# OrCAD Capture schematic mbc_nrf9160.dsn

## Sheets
1 01_BOARD: size Custom; rev: 1.0; note: 1.0
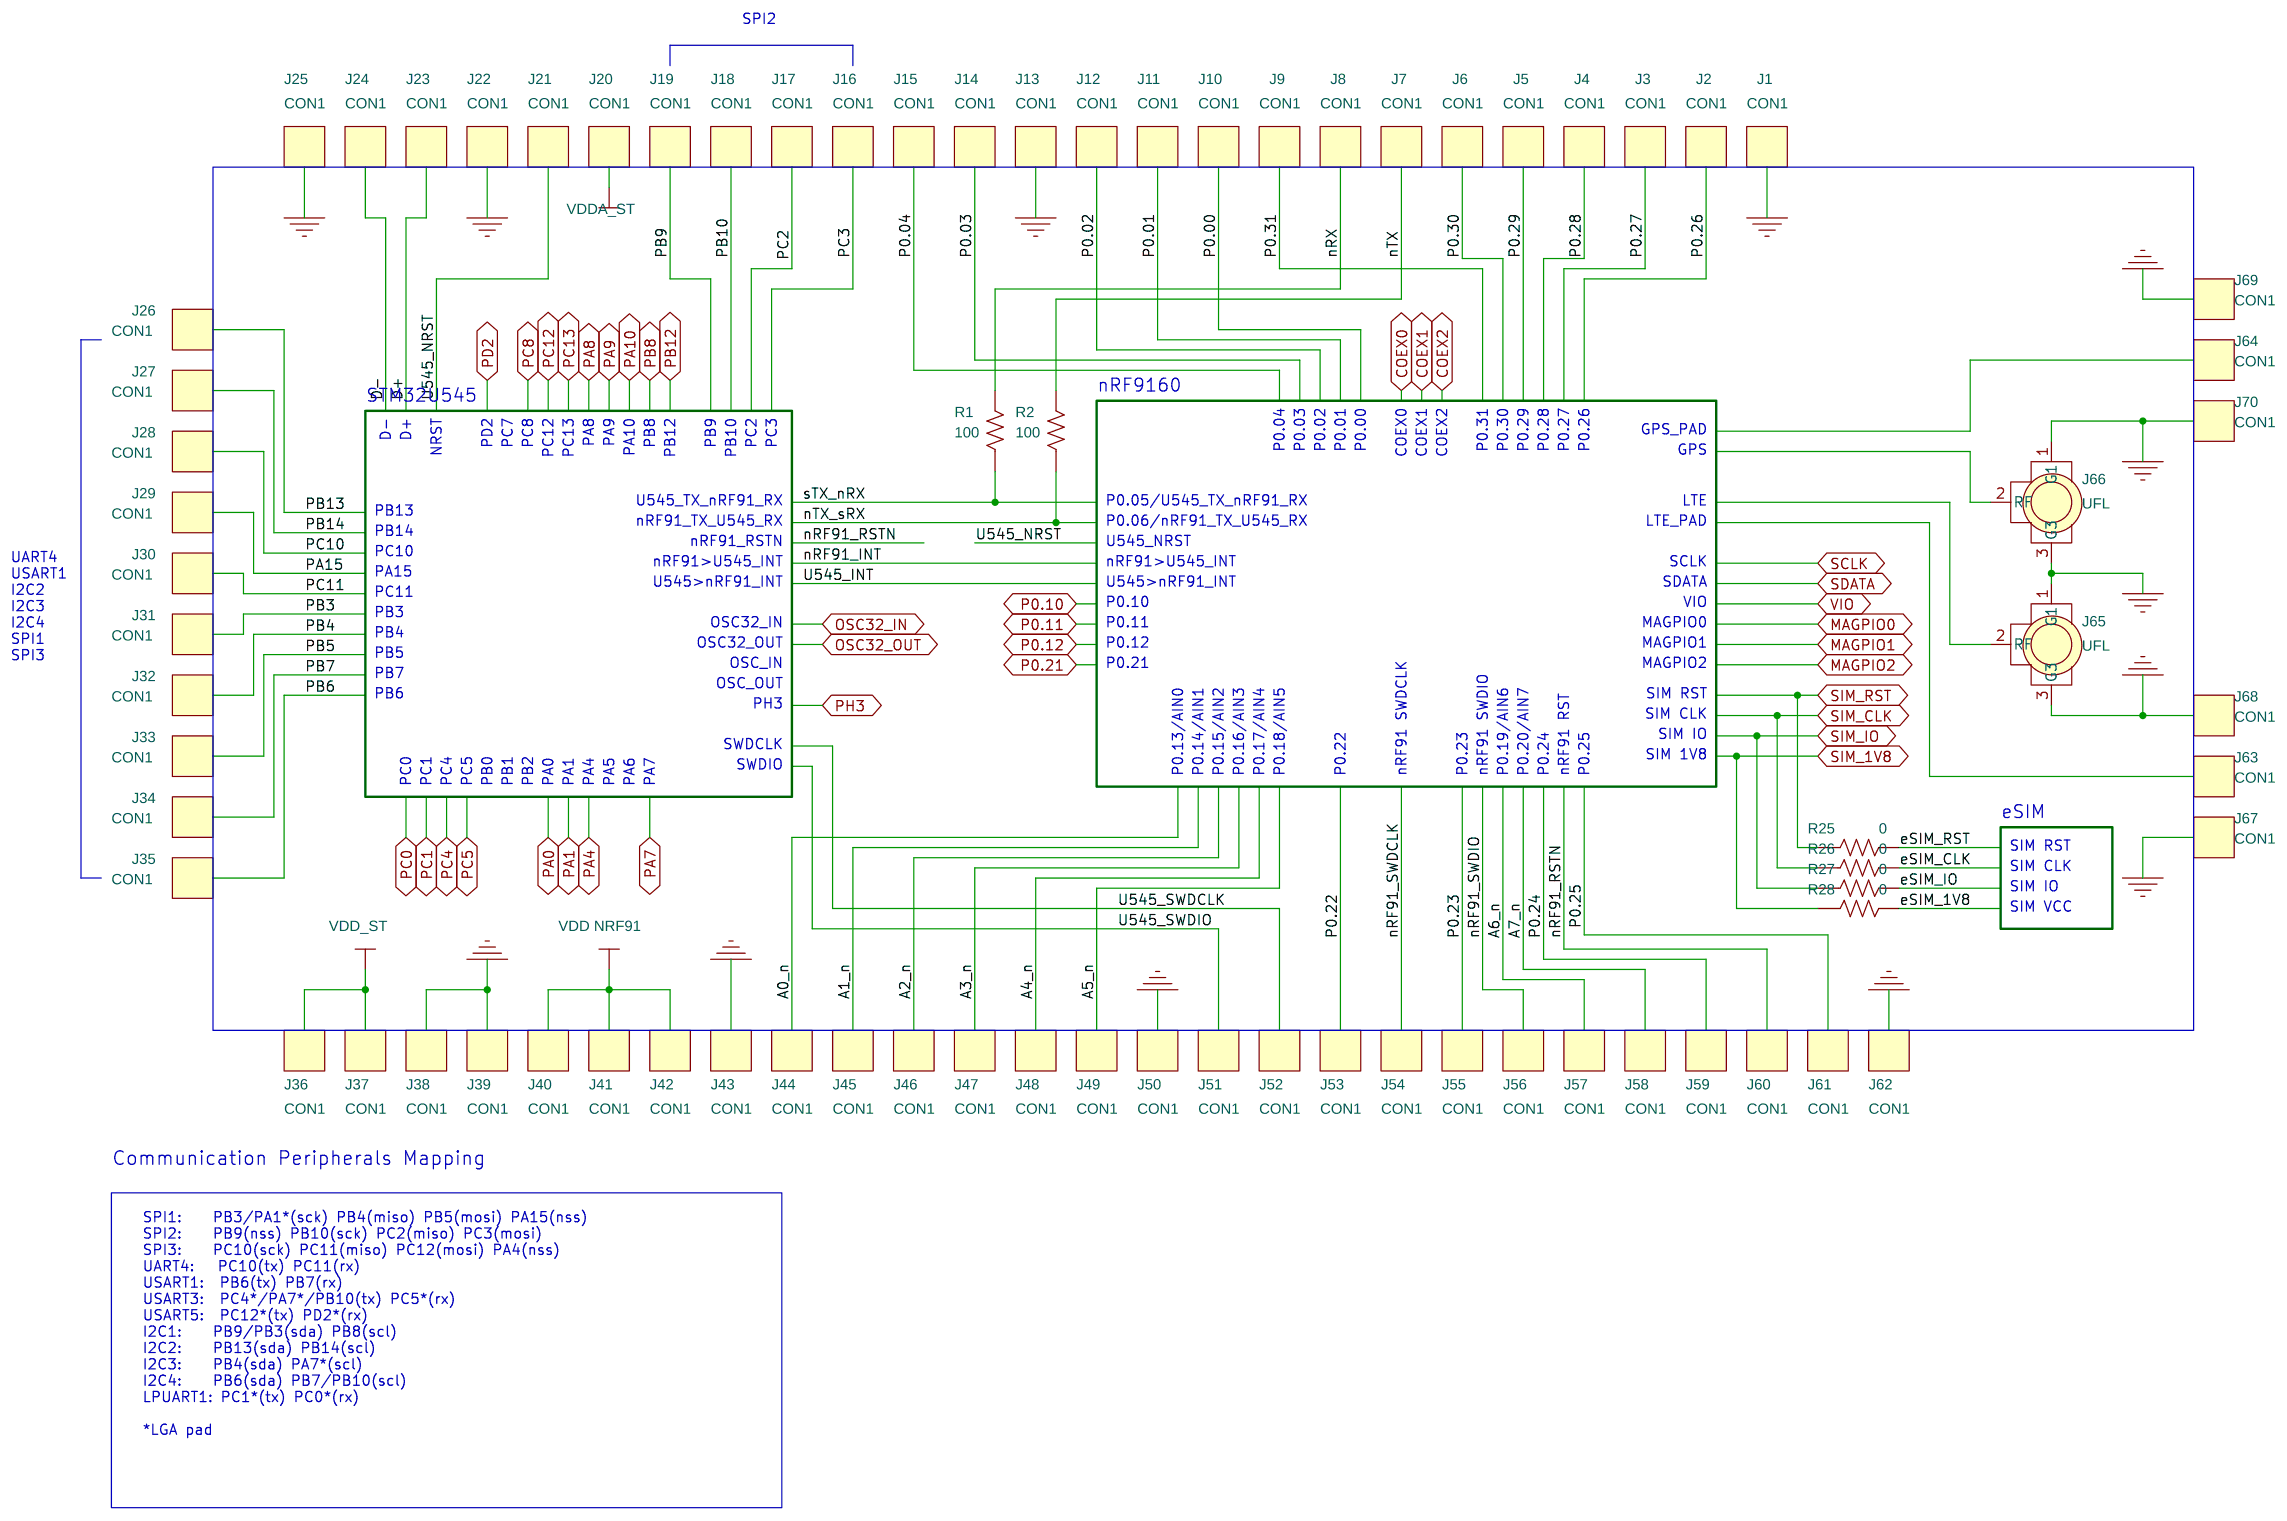
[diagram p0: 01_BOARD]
2 02_LGA: size Custom
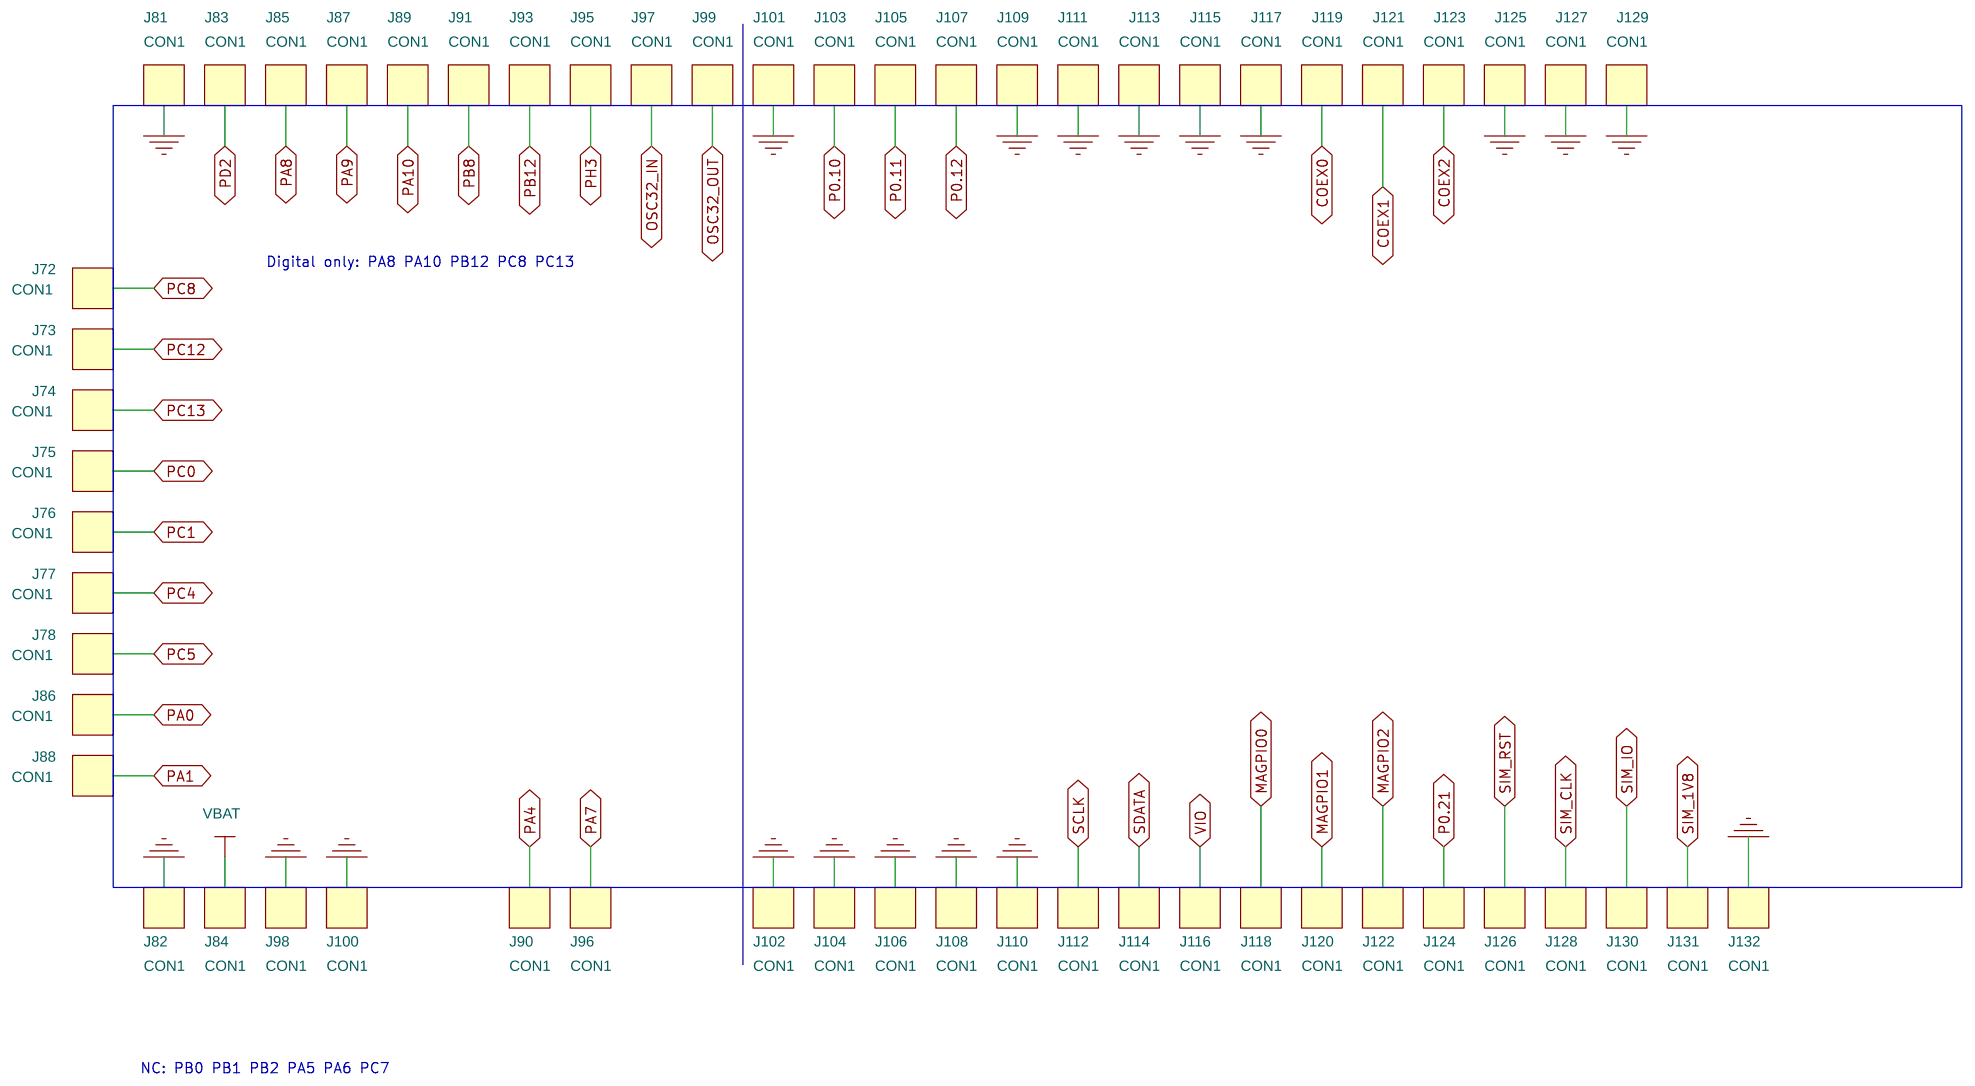
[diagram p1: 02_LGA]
3 eSIM: size A; block eSIM
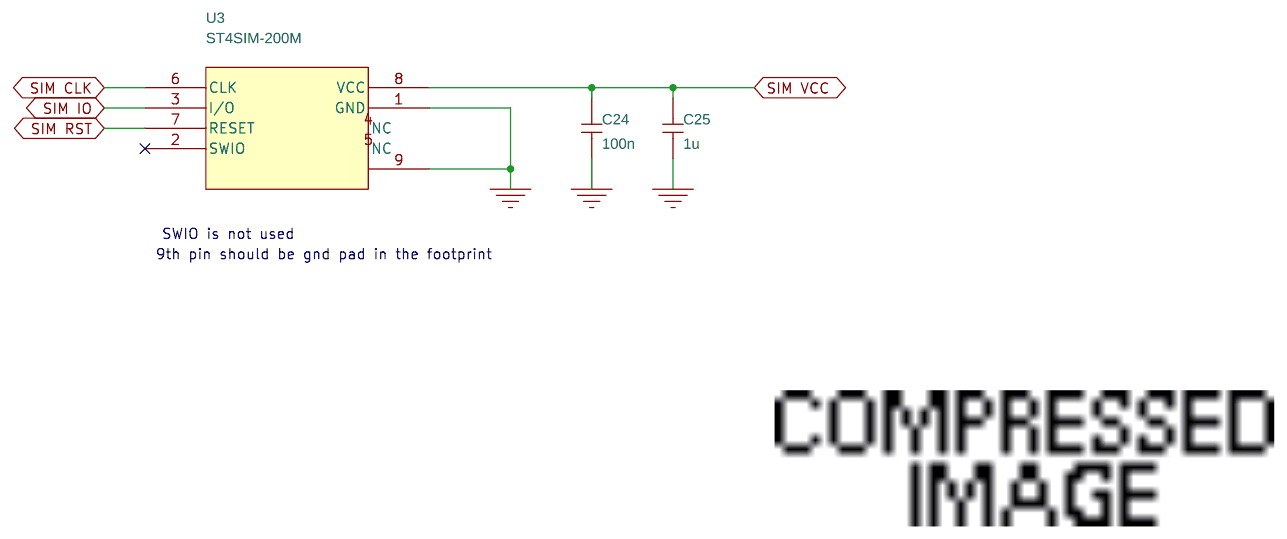
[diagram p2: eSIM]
4 NRF9160: size A; block nRF9160
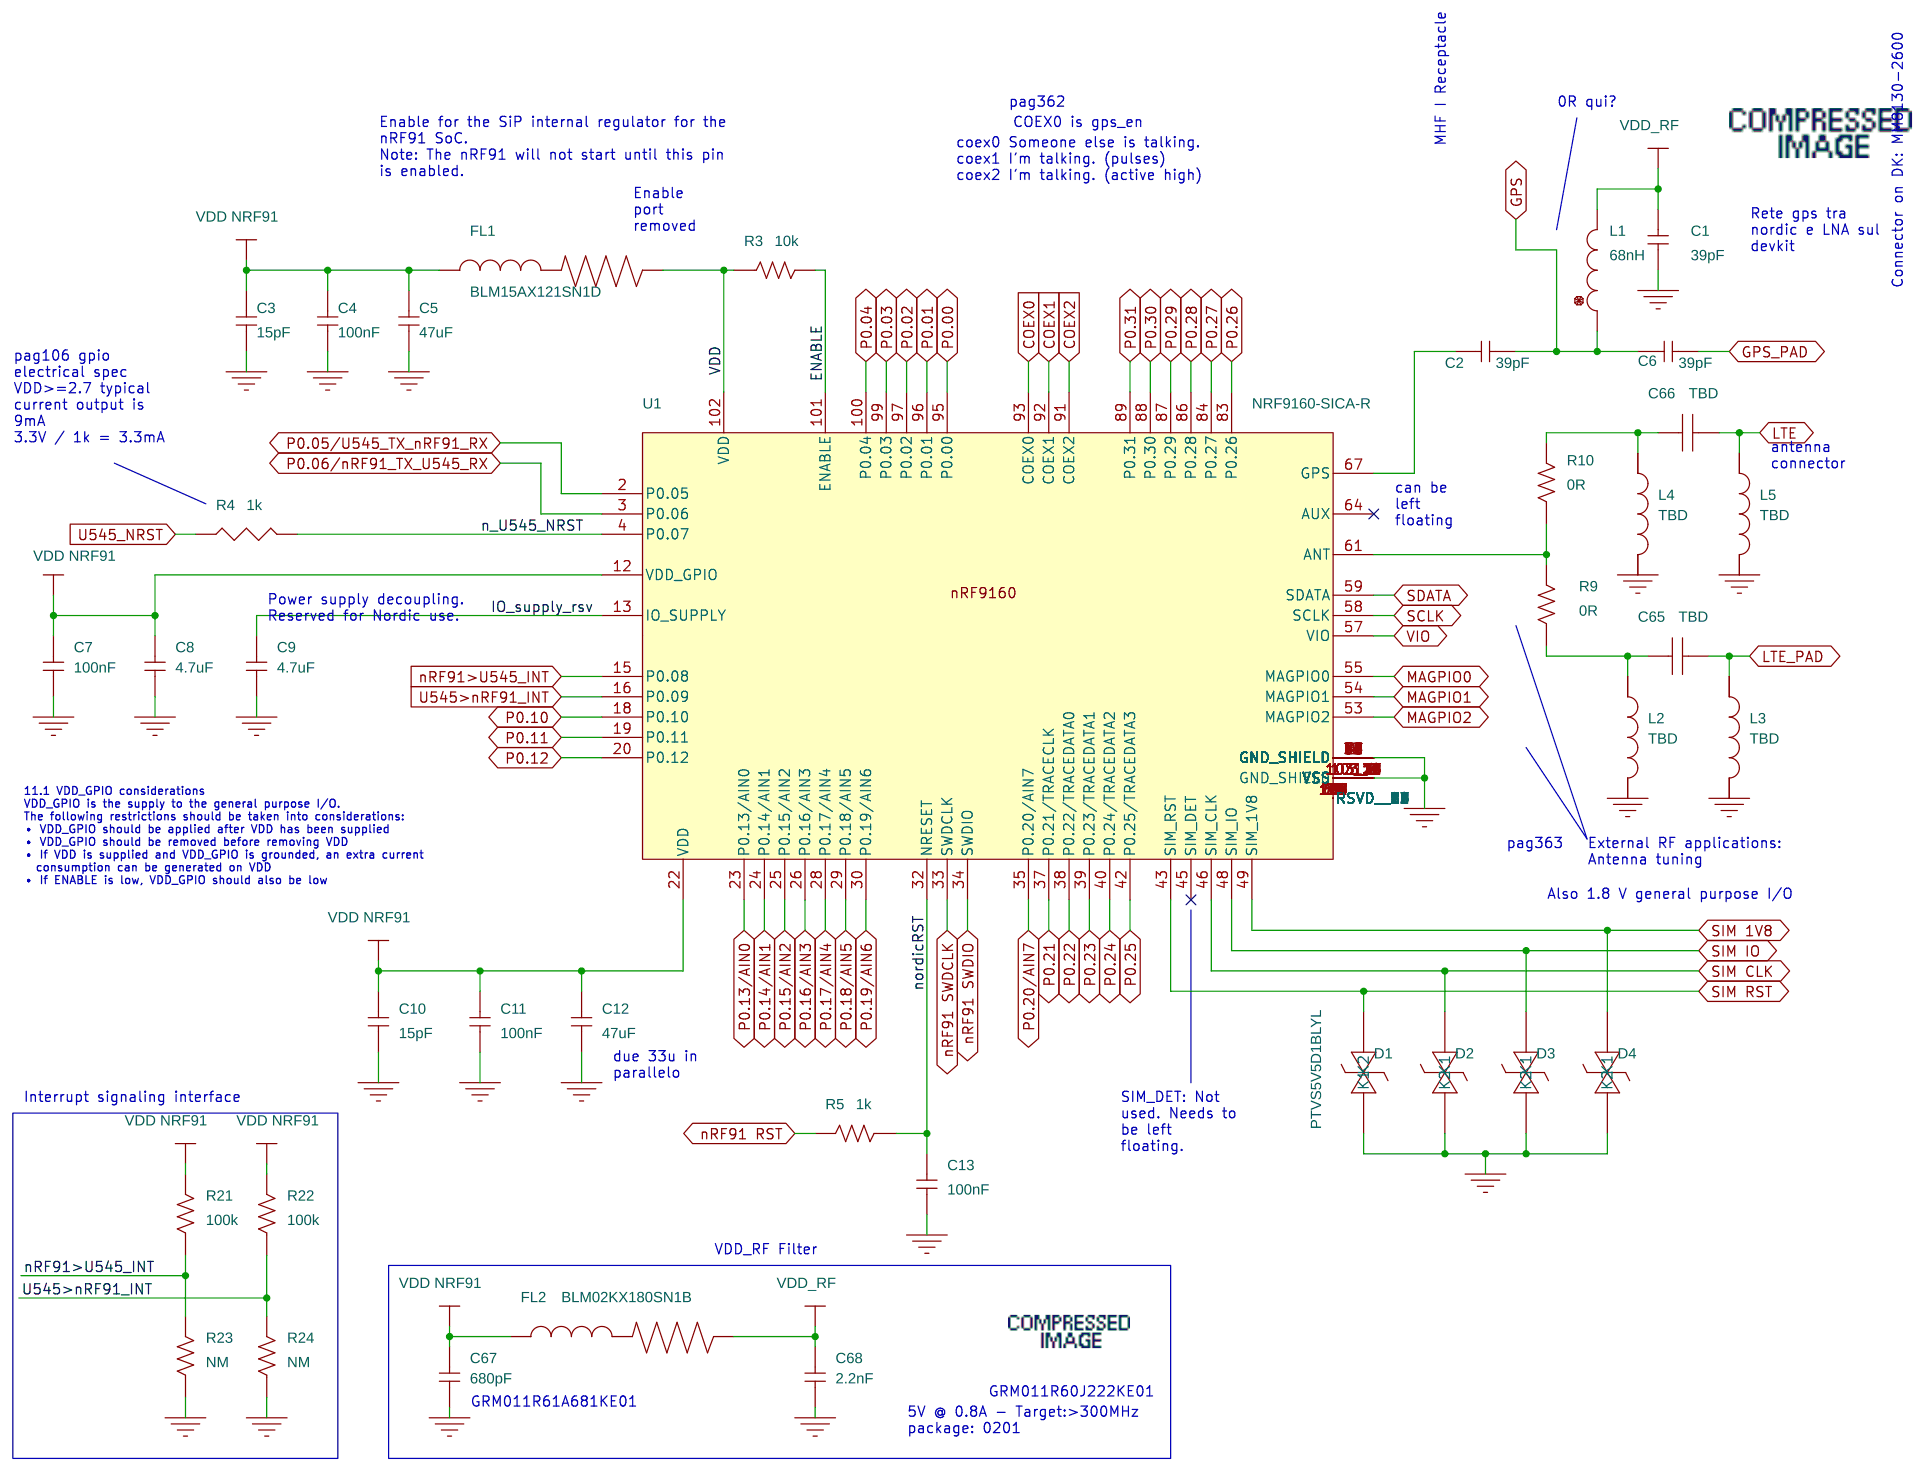
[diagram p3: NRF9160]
5 STM32U545: size A; block STM32U545
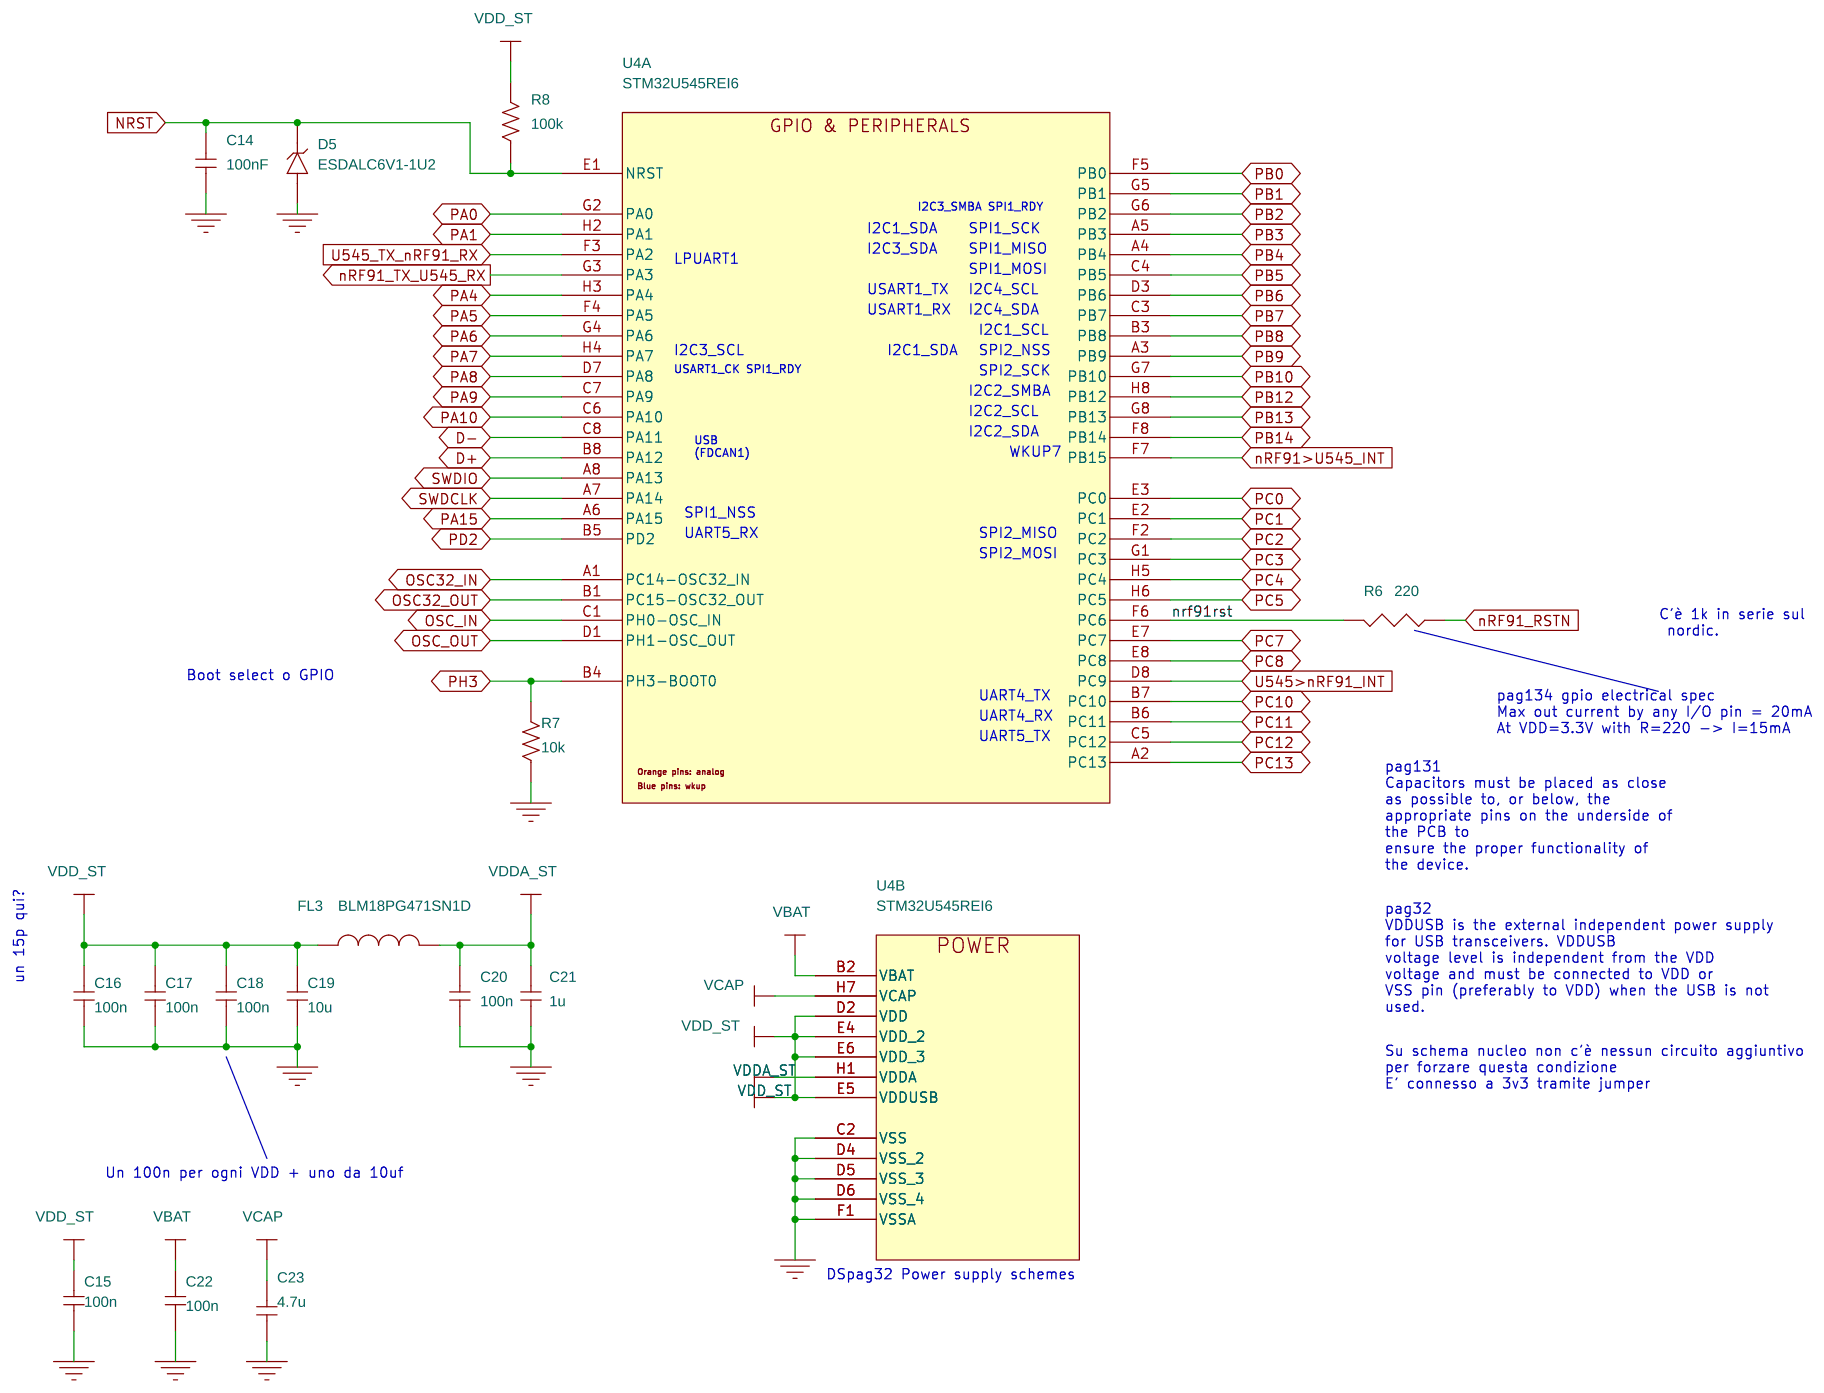
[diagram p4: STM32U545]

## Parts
sheet 01_BOARD
J1  CON1  [mbc_pad_conn]
J2  CON1  [mbc_pad_conn]
J3  CON1  [mbc_pad_conn]
J4  CON1  [mbc_pad_conn]
J5  CON1  [mbc_pad_conn]
J6  CON1  [mbc_pad_conn]
J7  CON1  [mbc_pad_conn]
J8  CON1  [mbc_pad_conn]
J9  CON1  [mbc_pad_conn]
J10  CON1  [mbc_pad_conn]
J11  CON1  [mbc_pad_conn]
J12  CON1  [mbc_pad_conn]
J13  CON1  [mbc_pad_conn]
J14  CON1  [mbc_pad_conn]
J15  CON1  [mbc_pad_conn]
J16  CON1  [mbc_pad_conn]
J17  CON1  [mbc_pad_conn]
J18  CON1  [mbc_pad_conn]
J19  CON1  [mbc_pad_conn]
J20  CON1  [mbc_pad_conn]
J21  CON1  [mbc_pad_conn]
J22  CON1  [mbc_pad_conn]
J23  CON1  [mbc_pad_conn]
J24  CON1  [mbc_pad_conn]
J25  CON1  [mbc_pad_conn]
J26  CON1  [mbc_pad_conn]
J27  CON1  [mbc_pad_conn]
J28  CON1  [mbc_pad_conn]
J29  CON1  [mbc_pad_conn]
J30  CON1  [mbc_pad_conn]
J31  CON1  [mbc_pad_conn]
J32  CON1  [mbc_pad_conn]
J33  CON1  [mbc_pad_conn]
J34  CON1  [mbc_pad_conn]
J35  CON1  [mbc_pad_conn]
J36  CON1  [mbc_pad_conn]
J37  CON1  [mbc_pad_conn]
J38  CON1  [mbc_pad_conn]
J39  CON1  [mbc_pad_conn]
J40  CON1  [mbc_pad_conn]
J41  CON1  [mbc_pad_conn]
J42  CON1  [mbc_pad_conn]
J43  CON1  [mbc_pad_conn]
J44  CON1  [mbc_pad_conn]
J45  CON1  [mbc_pad_conn]
J46  CON1  [mbc_pad_conn]
J47  CON1  [mbc_pad_conn]
J48  CON1  [mbc_pad_conn]
J49  CON1  [mbc_pad_conn]
J50  CON1  [mbc_pad_conn]
J51  CON1  [mbc_pad_conn]
J52  CON1  [mbc_pad_conn]
J53  CON1  [mbc_pad_conn]
J54  CON1  [mbc_pad_conn]
J55  CON1  [mbc_pad_conn]
J56  CON1  [mbc_pad_conn]
J57  CON1  [mbc_pad_conn]
J58  CON1  [mbc_pad_conn]
J59  CON1  [mbc_pad_conn]
J60  CON1  [mbc_pad_conn]
J61  CON1  [mbc_pad_conn]
J62  CON1  [mbc_pad_conn]
J63  CON1  [mbc_pad_conn]
J64  CON1  [mbc_pad_conn]
J65  UFL  [U_FL-R-SMT-1]
J66  UFL  [U_FL-R-SMT-1]
J67  CON1  [mbc_pad_conn]
J68  CON1  [mbc_pad_conn]
J69  CON1  [mbc_pad_conn]
J70  CON1  [mbc_pad_conn]
R1  100  [smr0201]
R2  100  [smr0201]
R25  0  [smr0201]
R26  0  [smr0201]
R27  0  [smr0201]
R28  0  [smr0201]
sheet 02_LGA
J72  CON1  [mbc_lga_small_pad]
J73  CON1  [mbc_lga_small_pad]
J74  CON1  [mbc_lga_small_pad]
J75  CON1  [mbc_lga_small_pad]
J76  CON1  [mbc_lga_small_pad]
J77  CON1  [mbc_lga_small_pad]
J78  CON1  [mbc_lga_small_pad]
J81  CON1  [mbc_lga_small_pad]
J82  CON1  [mbc_lga_small_pad]
J83  CON1  [mbc_lga_small_pad]
J84  CON1  [mbc_lga_small_pad]
J85  CON1  [mbc_lga_small_pad]
J86  CON1  [mbc_lga_small_pad]
J87  CON1  [mbc_lga_small_pad]
J88  CON1  [mbc_lga_small_pad]
J89  CON1  [mbc_lga_small_pad]
J90  CON1  [mbc_lga_small_pad]
J91  CON1  [mbc_lga_small_pad]
J93  CON1  [mbc_lga_small_pad]
J95  CON1  [mbc_lga_small_pad]
J96  CON1  [mbc_lga_small_pad]
J97  CON1  [mbc_lga_small_pad]
J98  CON1  [mbc_lga_small_pad]
J99  CON1  [mbc_lga_small_pad]
J100  CON1  [mbc_lga_small_pad]
J101  CON1  [mbc_lga_small_pad]
J102  CON1  [mbc_lga_small_pad]
J103  CON1  [mbc_lga_small_pad]
J104  CON1  [mbc_lga_small_pad]
J105  CON1  [mbc_lga_small_pad]
J106  CON1  [mbc_lga_small_pad]
J107  CON1  [mbc_lga_small_pad]
J108  CON1  [mbc_lga_small_pad]
J109  CON1  [mbc_lga_small_pad]
J110  CON1  [mbc_lga_small_pad]
J111  CON1  [mbc_lga_small_pad]
J112  CON1  [mbc_lga_small_pad]
J113  CON1  [mbc_lga_small_pad]
J114  CON1  [mbc_lga_small_pad]
J115  CON1  [mbc_lga_small_pad]
J116  CON1  [mbc_lga_small_pad]
J117  CON1  [mbc_lga_small_pad]
J118  CON1  [mbc_lga_small_pad]
J119  CON1  [mbc_lga_small_pad]
J120  CON1  [mbc_lga_small_pad]
J121  CON1  [mbc_lga_small_pad]
J122  CON1  [mbc_lga_small_pad]
J123  CON1  [mbc_lga_small_pad]
J124  CON1  [mbc_lga_small_pad]
J125  CON1  [mbc_lga_small_pad]
J126  CON1  [mbc_lga_small_pad]
J127  CON1  [mbc_lga_small_pad]
J128  CON1  [mbc_lga_small_pad]
J129  CON1  [mbc_lga_small_pad]
J130  CON1  [mbc_lga_small_pad]
J131  CON1  [mbc_lga_small_pad]
J132  CON1  [mbc_lga_small_pad]
sheet eSIM
C24  100n  [smc0402]
C25  1u  [smc0402]
U3  ST4SIM-200M  [SON_IM-200M_STM]
sheet NRF9160
C1  39pF  [smc0201]
C2  39pF  [smc0201]
C3  15pF  [smc0201]
C4  100nF  [smc0402]
C5  47uF  [smc0603]
C6  39pF  [smc0201]
C7  100nF  [smc0402]
C8  4.7uF  [smc0402]
C9  4.7uF  [smc0402]
C10  15pF  [smc0201]
C11  100nF  [smc0402]
C12  47uF  [smc0603]
C13  100nF  [smc0201]
C65  TBD  [smc0201]
C66  TBD  [smc0201]
C67  680pF  [smc0201]
C68  2.2nF  [smc0201]
D1  PTVS5V5D1BLYL  [PESD5V0S1BL315]
D2  PTVS5V5D1BLYL  [PESD5V0S1BL315]
D3  PTVS5V5D1BLYL  [PESD5V0S1BL315]
D4  PTVS5V5D1BLYL  [PESD5V0S1BL315]
FL1  BLM15AX121SN1D  [BEADC1005X55N]
FL2  BLM02KX180SN1B  [BEADC0402X32N]
L1  68nH  [sml0201]
L2  TBD  [sml0201]
L3  TBD  [sml0201]
L4  TBD  [sml0201]
L5  TBD  [sml0201]
R3  10k  [smr0201]
R4  1k  [smr0201]
R5  1k  [smr0201]
R9  0R  [smr0201]
R10  0R  [smr0201]
R21  100k  [smr0201]
R22  100k  [smr0201]
R23  NM  [smr0201]
R24  NM  [smr0201]
U1  NRF9160-SICA-R  [XCVR_NRF9160-SICA-R]
sheet STM32U545
C14  100nF  [smc0201]
C15  100n  [smc0402]
C16  100n  [smc0402]
C17  100n  [smc0402]
C18  100n  [smc0402]
C19  10u  [smc0603]
C20  100n  [smc0402]
C21  1u  [smc0402]
C22  100n  [smc0402]
C23  4.7u  [smc0402]
D5  ESDALC6V1-1U2  [DIODE_ESDALC6V1-1U2]
FL3  BLM18PG471SN1D  [sml0603]
R6  220  [smr0201]
R7  10k  [smr0201]
R8  100k  [smr0201]
U4  STM32U545REI6  [UFBGA64_5x5mm_STM]  (sections A,B)

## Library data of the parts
J1-J64 J67-J70 J72-J78 J81-J91 J93 J95-J132 = CON1_2
J65 J66 = UFL
R1-R3 R5 R7-R10 R21-R28 = R
C1-C25 C67 C68 = C
U3 = ST4SIM-200M_8
C65 C66 = CAP_NP_1
D1-D4 = PTVS5V5D1BLYL_0: Manufacturer Name: Nexperia; Source Id: SamacSys
FL1 = BLM15AX121SN1D: Manufacturer Name: Murata Electronics; Source Id: SnapEDA
FL2 = BLM02KX180SN1B: Manufacturer Name: Murata; Source Id: SnapEDA
L1 = L
FL3 L2-L5 = INDUCTOR
R4 R6 = R_0
U1 = myNRF9160-SICA-R_6
D5 = ESDALC6V1-1U2: Manufacturer Name: STMicroelectronics; Source Id: SnapEDA
U4 = STM32U545REI6_13

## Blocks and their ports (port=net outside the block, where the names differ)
STM32U545 = schematic STM32U545, on sheet 01_BOARD: D-, D+, U545_TX_nRF91_RX=sTX_nRX, nRF91_TX_U545_RX=nTX_sRX, nRF91_RSTN, NRST=U545_NRST, nRF91>U545_INT=nRF91_INT, U545>nRF91_INT=U545_INT, SWDCLK=U545_SWDCLK, SWDIO=U545_SWDIO, PA15, PB14, PB5, PA7, PB4, PB7, PB6, PB13, PC11, PC10, PB3, PB2=open, PH3, PC2, PB9, PC3, PB10, PB1=open, PB0=open, OSC_OUT=open, OSC32_OUT, OSC32_IN, OSC_IN=open, PA8, PA9, PA10, PC12, PC8, PD2, PB8, PC7=open, PB12, PC13, PC0, PC1, PC4, PC5, PA4, PA5=open, PA6=open, PA0, PA1
eSIM = schematic ST4SIM-200M, on sheet 01_BOARD: SIM CLK=eSIM_CLK, SIM VCC=eSIM_1V8, SIM IO=eSIM_IO, SIM RST=eSIM_RST
nRF9160 = schematic NRF9160, on sheet 01_BOARD: P0.13/AIN0=A0_n, P0.14/AIN1=A1_n, P0.15/AIN2=A2_n, P0.16/AIN3=A3_n, P0.17/AIN4=A4_n, P0.18/AIN5=A5_n, P0.19/AIN6=A6_n, P0.20/AIN7=A7_n, P0.21, P0.22, P0.23, P0.24, P0.25, P0.10, P0.11, P0.12, P0.04, P0.03, P0.02, P0.01, P0.00, P0.31, P0.30, P0.29, P0.28, P0.27, P0.26, nRF91 RST=nRF91_RSTN, nRF91 SWDCLK=nRF91_SWDCLK, nRF91 SWDIO=nRF91_SWDIO, SIM RST=SIM_RST, SIM CLK=SIM_CLK, SIM IO=SIM_IO, SIM 1V8=SIM_1V8, SDATA, SCLK, VIO, P0.05/U545_TX_nRF91_RX=sTX_nRX, P0.06/nRF91_TX_U545_RX=nTX_sRX, nRF91>U545_INT=nRF91_INT, U545>nRF91_INT=U545_INT, U545_NRST, COEX0, COEX1, COEX2, MAGPIO2, MAGPIO0, MAGPIO1, LTE=N13625908, LTE_PAD=N13629219, GPS=N13629615, GPS_PAD=N13629622

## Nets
GND: C1.1 C3.1 C4.1 C5.1 C7.1 C8.1 C9.1 C10.1 C11.1 C12.1 C13.1 C14.1 C15.1 C16.1 C17.1 C18.1 C19.1 C20.1 C21.1 C22.1 C23.1 C24.1 C25.1 C67.1 C68.1 D1.1(K1) D2.2(K2) D3.2(K2) D4.2(K2) D5.2(A) J1.1 J13.1 J22.1 J25.1 J38.1 J39.1 J43.1 J50.1 J62.1 J65.1(G1) J65.3(G3) J66.1(G1) J66.3(G3) J67.1 J68.1 J69.1 J70.1 J81.1 J82.1 J98.1 J100.1 J101.1 J102.1 J104.1 J106.1 J108.1 J109.1 J110.1 J111.1 J113.1 J115.1 J117.1 J125.1 J127.1 J129.1 J132.1 L2.2 L3.2 L4.2 L5.2 R7.1 R23.1 R24.1 U1.1(GND_SHIELD) U1.103_1(VSS) U3.1(GND) U3.9 U4.C2(VSS) U4.D4(VSS_2) U4.D5(VSS_3) U4.D6(VSS_4) U4.F1(VSSA)
nRF9160/GND_SHIELD: U1.5(GND_SHIELD) U1.9(GND_SHIELD) U1.14(GND_SHIELD) U1.17(GND_SHIELD) U1.21(GND_SHIELD) U1.27(GND_SHIELD) U1.31(GND_SHIELD) U1.36(GND_SHIELD) U1.41(GND_SHIELD) U1.44(GND_SHIELD) U1.47(GND_SHIELD) U1.50(GND_SHIELD) U1.52(GND_SHIELD) U1.56(GND_SHIELD) U1.60(GND_SHIELD) U1.62(GND_SHIELD) U1.63(GND_SHIELD) U1.65(GND_SHIELD) U1.66(GND_SHIELD) U1.72(GND_SHIELD) U1.74(GND_SHIELD) U1.75(GND_SHIELD) U1.76(GND_SHIELD) U1.77(GND_SHIELD) U1.78(GND_SHIELD) U1.79(GND_SHIELD) U1.80(GND_SHIELD) U1.81(GND_SHIELD) U1.82(GND_SHIELD) U1.85(GND_SHIELD) U1.90(GND_SHIELD) U1.94(GND_SHIELD) U1.98(GND_SHIELD)
nRF9160/VDD: FL1.2 R3.1 U1.102(VDD)
nRF9160/VSS: U1.103_2(VSS) U1.103_3(VSS) U1.103_4(VSS) U1.103_5(VSS) U1.103_6(VSS) U1.103_7(VSS) U1.103_8(VSS) U1.103_9(VSS) U1.103_10(VSS) U1.103_11(VSS) U1.103_12(VSS) U1.103_13(VSS) U1.103_14(VSS) U1.103_15(VSS) U1.103_16(VSS) U1.103_17(VSS) U1.103_18(VSS) U1.103_19(VSS) U1.103_20(VSS) U1.103_21(VSS) U1.103_22(VSS) U1.103_23(VSS) U1.103_24(VSS) U1.103_25(VSS) U1.103_26(VSS) U1.103_27(VSS) U1.103_28(VSS) U1.103_29(VSS) U1.103_30(VSS) U1.103_31(VSS) U1.103_32(VSS) U1.103_33(VSS) U1.103_34(VSS) U1.103_35(VSS)
VBAT: C22.2 J84.1 U4.B2(VBAT)
VDD nRF91: C3.2 C4.2 C5.2 C7.2 C8.2 C10.2 C11.2 C12.2 C67.2 FL1.1 FL2.1 J40.1 J41.1 J42.1 R21.2 R22.2 U1.12(VDD_GPIO) U1.22(VDD)
VDD_RF: C1.2 C68.2 FL2.2 L1.2
VDD_ST: C15.2 C16.2 C17.2 C18.2 C19.2 FL3.1 J36.1 J37.1 R8.2 U4.D2(VDD) U4.E4(VDD_2) U4.E5(VDDUSB) U4.E6(VDD_3)
VDDA_ST: C20.2 C21.2 FL3.2 J20.1 U4.H1(VDDA)
A0_n: J44.1 U1.23(P0.13/AIN0)
A1_n: J45.1 U1.24(P0.14/AIN1)
A2_n: J46.1 U1.25(P0.15/AIN2)
A3_n: J47.1 U1.26(P0.16/AIN3)
A4_n: J48.1 U1.28(P0.17/AIN4)
A5_n: J49.1 U1.29(P0.18/AIN5)
A6_n: J57.1 U1.30(P0.19/AIN6)
A7_n: J58.1 U1.35(P0.20/AIN7)
COEX0: J119.1 U1.93(COEX0)
COEX1: J121.1 U1.92(COEX1)
COEX2: J123.1 U1.91(COEX2)
D+: J23.1 U4.B8(PA12)
D-: J24.1 U4.C8(PA11)
eSIM_1V8: C24.2 C25.2 R28.2 U3.8(VCC)
eSIM_CLK: R26.2 U3.6(CLK)
eSIM_IO: R27.2 U3.3(I/O)
eSIM_RST: R25.2 U3.7(RESET)
MAGPIO0: J118.1 U1.55(MAGPIO0)
MAGPIO1: J120.1 U1.54(MAGPIO1)
MAGPIO2: J122.1 U1.53(MAGPIO2)
NC: U3.4(NC) U3.5(NC)
nRF91_INT: R21.1 R23.2 U1.15(P0.08) U4.F7(PB15)
nRF91_RSTN: J60.1 R5.2 R6.1
nRF91_SWDCLK: J54.1 U1.33(SWDCLK)
nRF91_SWDIO: J56.1 U1.34(SWDIO)
nRF9160/ENABLE: R3.2 U1.101(ENABLE)
nRF9160/IO_supply_rsv: C9.2 U1.13(IO_SUPPLY)
nRF9160/n_U545_NRST: R4.2 U1.4(P0.07)
nRF9160/nordicRST: C13.2 R5.1 U1.32(NRESET)
nRX: J8.1 R1.2
nTX: J7.1 R2.2
nTX_sRX: R2.1 U1.3(P0.06) U4.G3(PA3)
OSC32_IN: J97.1 U4.A1(PC14-OSC32_IN)
OSC32_OUT: J99.1 U4.B1(PC15-OSC32_OUT)
P0.00: J10.1 U1.95(P0.00)
P0.01: J11.1 U1.96(P0.01)
P0.02: J12.1 U1.97(P0.02)
P0.03: J14.1 U1.99(P0.03)
P0.04: J15.1 U1.100(P0.04)
P0.10: J103.1 U1.18(P0.10)
P0.11: J105.1 U1.19(P0.11)
P0.12: J107.1 U1.20(P0.12)
P0.21: J124.1 U1.37(P0.21/TRACECLK)
P0.22: J53.1 U1.38(P0.22/TRACEDATA0)
P0.23: J55.1 U1.39(P0.23/TRACEDATA1)
P0.24: J59.1 U1.40(P0.24/TRACEDATA2)
P0.25: J61.1 U1.42(P0.25/TRACEDATA3)
P0.26: J2.1 U1.83(P0.26)
P0.27: J3.1 U1.84(P0.27)
P0.28: J4.1 U1.86(P0.28)
P0.29: J5.1 U1.87(P0.29)
P0.30: J6.1 U1.88(P0.30)
P0.31: J9.1 U1.89(P0.31)
PA0: J86.1 U4.G2(PA0)
PA1: J88.1 U4.H2(PA1)
PA4: J90.1 U4.H3(PA4)
PA7: J96.1 U4.H4(PA7)
PA8: J85.1 U4.D7(PA8)
PA9: J87.1 U4.C7(PA9)
PA10: J89.1 U4.C6(PA10)
PA15: J29.1 U4.A6(PA15)
PB3: J31.1 U4.A5(PB3)
PB4: J32.1 U4.A4(PB4)
PB5: J33.1 U4.C4(PB5)
PB6: J35.1 U4.D3(PB6)
PB7: J34.1 U4.C3(PB7)
PB8: J91.1 U4.B3(PB8)
PB9: J19.1 U4.A3(PB9)
PB10: J18.1 U4.G7(PB10)
PB12: J93.1 U4.H8(PB12)
PB13: J26.1 U4.G8(PB13)
PB14: J27.1 U4.F8(PB14)
PC0: J75.1 U4.E3(PC0)
PC1: J76.1 U4.E2(PC1)
PC2: J17.1 U4.F2(PC2)
PC3: J16.1 U4.G1(PC3)
PC4: J77.1 U4.H5(PC4)
PC5: J78.1 U4.H6(PC5)
PC8: J72.1 U4.E8(PC8)
PC10: J28.1 U4.B7(PC10)
PC11: J30.1 U4.B6(PC11)
PC12: J73.1 U4.C5(PC12)
PC13: J74.1 U4.A2(PC13)
PD2: J83.1 U4.B5(PD2)
PH3: J95.1 R7.2 U4.B4(PH3-BOOT0)
RSVD: U1.6(RSVD)
RSVD__1: U1.7(RSVD__1)
RSVD__2: U1.8(RSVD__2)
RSVD__3: U1.10(RSVD__3)
RSVD__4: U1.11(RSVD__4)
RSVD__5: U1.51(RSVD__5)
RSVD__6: U1.68(RSVD__6)
RSVD__7: U1.69(RSVD__7)
RSVD__8: U1.70(RSVD__8)
RSVD__9: U1.71(RSVD__9)
RSVD__10: U1.73(RSVD__10)
RSVD__11: U1.104(RSVD__11)
RSVD__12: U1.105(RSVD__12)
RSVD__13: U1.106(RSVD__13)
RSVD__14: U1.107(RSVD__14)
RSVD__15: U1.108(RSVD__15)
RSVD__16: U1.109(RSVD__16)
RSVD__17: U1.110(RSVD__17)
RSVD__18: U1.111(RSVD__18)
RSVD__19: U1.112(RSVD__19)
RSVD__20: U1.113(RSVD__20)
RSVD__21: U1.114(RSVD__21)
RSVD__22: U1.115(RSVD__22)
RSVD__23: U1.116(RSVD__23)
RSVD__24: U1.117(RSVD__24)
RSVD__25: U1.118(RSVD__25)
RSVD__26: U1.119(RSVD__26)
RSVD__27: U1.120(RSVD__27)
RSVD__28: U1.121(RSVD__28)
RSVD__29: U1.122(RSVD__29)
RSVD__30: U1.123(RSVD__30)
RSVD__31: U1.124(RSVD__31)
RSVD__32: U1.125(RSVD__32)
RSVD__33: U1.126(RSVD__33)
RSVD__34: U1.127(RSVD__34)
SCLK: J112.1 U1.58(SCLK)
SDATA: J114.1 U1.59(SDATA)
SIM_1V8: D4.1(K1) J131.1 R28.1 U1.49(SIM_1V8)
SIM_CLK: D2.1(K1) J128.1 R26.1 U1.46(SIM_CLK)
SIM_IO: D3.1(K1) J130.1 R27.1 U1.48(SIM_IO)
SIM_RST: D1.2(K2) J126.1 R25.1 U1.43(SIM_RST)
STM32U545/nrf91rst: R6.2 U4.F6(PC6)
STM32U545/OSC_IN: U4.C1(PH0-OSC_IN)
STM32U545/OSC_OUT: U4.D1(PH1-OSC_OUT)
STM32U545/PA5: U4.F4(PA5)
STM32U545/PA6: U4.G4(PA6)
STM32U545/PB0: U4.F5(PB0)
STM32U545/PB1: U4.G5(PB1)
STM32U545/PB2: U4.G6(PB2)
STM32U545/PC7: U4.E7(PC7)
sTX_nRX: R1.1 U1.2(P0.05) U4.F3(PA2)
U545_INT: R22.1 R24.2 U1.16(P0.09) U4.D8(PC9)
U545_NRST: C14.2 D5.1(K) J21.1 R4.1 R8.1 U4.E1(NRST)
U545_SWDCLK: J52.1 U4.A7(PA14)
U545_SWDIO: J51.1 U4.A8(PA13)
VCAP: C23.2 U4.H7(VCAP)
VIO: J116.1 U1.57(VIO)
N13625908: C66.2 J65.2(RF) L5.1
N13629219: C65.2 J63.1 L3.1
N13629615: C2.1 C6.2 J66.2(RF) L1.1
N13629622: C6.1 J64.1
nRF9160/N13496579: C2.2 U1.67(GPS)
nRF9160/N13657158: R9.2 R10.1 U1.61(ANT)
nRF9160/N13657162: C65.1 L2.1 R9.1
nRF9160/N13659178: C66.1 L4.1 R10.2

Not connected (* = marked no-connect by the designer): U1 45(SIM_DET)* 64(AUX)*; U3 2(SWIO)*

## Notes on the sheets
sheet 1
- SPI2
- UART4
  USART1
  I2C2
  I2C3
  I2C4
  SPI1
  SPI3
- Communication Peripherals Mapping
- SPI1:    PB3/PA1*(sck) PB4(miso) PB5(mosi) PA15(nss)
  SPI2:    PB9(nss) PB10(sck) PC2(miso) PC3(mosi)
  SPI3:    PC10(sck) PC11(miso) PC12(mosi) PA4(nss)
  UART4:   PC10(tx) PC11(rx)
  USART1:  PB6(tx) PB7(rx)
  USART3:  PC4*/PA7*/PB10(tx) PC5*(rx)
  USART5:  PC12*(tx) PD2*(rx)
  I2C1:    PB9/PB3(sda) PB8(scl)
  I2C2:    PB13(sda) PB14(scl)
  I2C3:    PB4(sda) PA7*(scl)
  I2C4:    PB6(sda) PB7/PB10(scl)
  LPUART1: PC1*(tx) PC0*(rx)
  *LGA pad
sheet 2
- Digital only: PA8 PA10 PB12 PC8 PC13
- NC: PB0 PB1 PB2 PA5 PA6 PC7
sheet 3
- SWIO is not used
- 9th pin should be gnd pad in the footprint
sheet 4
- pag362
- 0R qui?
- Enable for the SiP internal regulator for the
  nRF91 SoC.
  Note: The nRF91 will not start until this pin
  is enabled.
- COEX0 is gps_en
- coex0 Someone else is talking.
  coex1 I'm talking. (pulses)
  coex2 I'm talking. (active high)
- MHF I Receptacle
- Enable
  port
  removed
- Rete gps tra
  nordic e LNA sul
  devkit
- Connector on DK: MM8130-2600
- pag106 gpio
  electrical spec
  VDD>=2.7 typical
  current output is
  9mA
  3.3V / 1k = 3.3mA
- antenna
  connector
- can be
  left
  floating
- Power supply decoupling.
  Reserved for Nordic use.
- 11.1 VDD_GPIO considerations
  VDD_GPIO is the supply to the general purpose I/O.
  The following restrictions should be taken into considerations:
  • VDD_GPIO should be applied after VDD has been supplied
  • VDD_GPIO should be removed before removing VDD
  • If VDD is supplied and VDD_GPIO is grounded, an extra current
    consumption can be generated on VDD
  • If ENABLE is low, VDD_GPIO should also be low
- pag363
- External RF applications:
  Antenna tuning
- Also 1.8 V general purpose I/O
- due 33u in
  parallelo
- Interrupt signaling interface
- SIM_DET: Not
  used. Needs to
  be left
  floating.
- VDD_RF Filter
- GRM011R61A681KE01
- GRM011R60J222KE01
- 5V @ 0.8A - Target:>300MHz
  package: 0201
sheet 5
- I2C1_SDA
- I2C3_SMBA SPI1_RDY
- SPI1_SCK
- I2C3_SDA
- SPI1_MISO
- LPUART1
- SPI1_MOSI
- USART1_TX
- I2C4_SCL
- USART1_RX
- I2C4_SDA
- I2C3_SCL
- I2C1_SDA
- I2C1_SCL
- SPI2_NSS
- USART1_CK SPI1_RDY
- SPI2_SCK
- I2C2_SMBA
- I2C2_SCL
- USB
  (FDCAN1)
- I2C2_SDA
- WKUP7
- SPI1_NSS
- UART5_RX
- SPI2_MISO
- SPI2_MOSI
- C'è 1k in serie sul
   nordic.
- Boot select o GPIO
- UART4_TX
- pag134 gpio electrical spec
  Max out current by any I/O pin = 20mA
  At VDD=3.3V with R=220 -> I=15mA
- UART4_RX
- UART5_TX
- pag131
  Capacitors must be placed as close
  as possible to, or below, the
  appropriate pins on the underside of
  the PCB to
  ensure the proper functionality of
  the device.
- pag32
  VDDUSB is the external independent power supply
  for USB transceivers. VDDUSB
  voltage level is independent from the VDD
  voltage and must be connected to VDD or
  VSS pin (preferably to VDD) when the USB is not
  used.
- un 15p qui?
- Su schema nucleo non c'è nessun circuito aggiuntivo
  per forzare questa condizione
  E' connesso a 3v3 tramite jumper
- Un 100n per ogni VDD + uno da 10uf
- DSpag32 Power supply schemes
